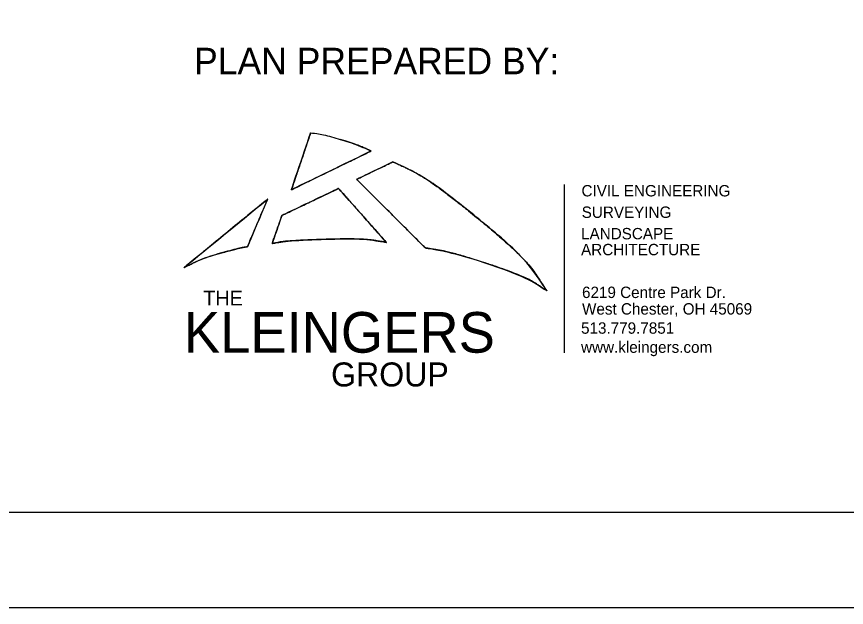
# Model space of a CAD drawing. Extents: x 44.2 to 78.2, y 4.5 to 26.5.
# Drawn here: x 46.547 to 50.92, y 4.501 to 7.613 of the extents above; entities that cross this region are included whole.
import ezdxf

# ---------------------------------------------------------------- set-up
doc = ezdxf.new("R2010")
doc.units = 0
for name, color, linetype in [('SH_Border', 7, 'Continuous'), ('SH_Cut_Line', 7, 'Continuous'), ('SH_Text', 7, 'Continuous')]:
    doc.layers.add(name, color=color, linetype=linetype)

msp = doc.modelspace()

# ---------------------------------------------------------------- linework, layer by layer
at = {"layer": 'SH_Border'}
msp.add_lwpolyline([(45.7359, 26.0014), (77.7359, 26.0014), (77.7359, 5.0014), (45.7359, 5.0014)], close=True, dxfattribs=at)
at = {"layer": 'SH_Cut_Line'}
msp.add_lwpolyline([(44.2359, 4.5014), (78.2359, 4.5014), (78.2359, 26.5014), (44.2359, 26.5014)], close=True, dxfattribs=at)
at = {"layer": 'SH_Text'}
msp.add_lwpolyline([(49.4332, 6.7295), (49.4332, 5.8423)], dxfattribs=at)
for points, degree in [([(48.0961, 7.0007), (48.0961, 7.0007), (47.9952, 6.7014), (47.9952, 6.7014)], 2), ([(48.4147, 6.905), (48.4147, 6.905), (48.3457, 6.9381), (48.2523, 6.9661), (48.159, 6.9941), (48.0961, 7.0007), (48.0961, 7.0007), (48.0961, 7.0007), (47.9952, 6.7014), (47.9952, 6.7014), (47.9952, 6.7014), (48.4147, 6.905), (48.4147, 6.905)], 3), ([(48.4147, 6.905), (48.4147, 6.905), (48.3457, 6.9381), (48.2523, 6.9661)], 2), ([(47.9952, 6.7014), (47.9952, 6.7014), (48.4147, 6.905), (48.4147, 6.905)], 2), ([(48.339, 6.7559), (48.339, 6.7559), (48.5295, 6.848), (48.5295, 6.848)], 2), ([(49.0087, 6.3182), (48.8407, 6.3724), (48.7005, 6.395), (48.7005, 6.395), (48.7005, 6.395), (48.339, 6.7559), (48.339, 6.7559), (48.339, 6.7559), (48.5295, 6.848), (48.5295, 6.848), (48.5295, 6.848), (48.7102, 6.7656), (48.9282, 6.5904), (49.2152, 6.3598), (49.3405, 6.1696), (49.3405, 6.1696), (49.3405, 6.1696), (49.2186, 6.2503), (49.0087, 6.3182)], 3), ([(48.5295, 6.848), (48.5295, 6.848), (48.7102, 6.7656), (48.9282, 6.5904)], 2), ([(48.7005, 6.395), (48.7005, 6.395), (48.339, 6.7559), (48.339, 6.7559)], 2), ([(48.2431, 6.7081), (48.2431, 6.7081), (48.495, 6.4242), (48.495, 6.4242), (48.495, 6.4242), (48.3623, 6.446), (48.1785, 6.4403), (47.9751, 6.4339), (47.8931, 6.4176), (47.8931, 6.4176), (47.8931, 6.4176), (47.945, 6.566), (47.945, 6.566), (47.945, 6.566), (48.2431, 6.7081), (48.2431, 6.7081)], 3), ([(47.945, 6.566), (47.945, 6.566), (48.2431, 6.7081), (48.2431, 6.7081)], 2), ([(48.2431, 6.7081), (48.2431, 6.7081), (48.495, 6.4242), (48.495, 6.4242)], 2), ([(47.8695, 6.6517), (47.8695, 6.6517), (47.428, 6.2904), (47.428, 6.2904)], 2), ([(47.8695, 6.6517), (47.8695, 6.6517), (47.428, 6.2904), (47.428, 6.2904), (47.428, 6.2904), (47.5272, 6.3411), (47.6346, 6.3706), (47.7313, 6.3972), (47.7632, 6.4008), (47.7632, 6.4008), (47.7632, 6.4008), (47.8695, 6.6517), (47.8695, 6.6517)], 3), ([(47.7632, 6.4008), (47.7632, 6.4008), (47.8695, 6.6517), (47.8695, 6.6517)], 2), ([(47.8931, 6.4176), (47.8931, 6.4176), (47.945, 6.566), (47.945, 6.566)], 2), ([(48.9282, 6.5904), (49.2152, 6.3598), (49.3405, 6.1696), (49.3405, 6.1696)], 2), ([(48.1785, 6.4403), (47.9751, 6.4339), (47.8931, 6.4176), (47.8931, 6.4176)], 2), ([(48.495, 6.4242), (48.495, 6.4242), (48.3623, 6.446), (48.1785, 6.4403)], 2), ([(47.6346, 6.3706), (47.7313, 6.3972), (47.7632, 6.4008), (47.7632, 6.4008)], 2), ([(49.0087, 6.3182), (48.8407, 6.3724), (48.7005, 6.395), (48.7005, 6.395)], 2), ([(47.428, 6.2904), (47.428, 6.2904), (47.5272, 6.3411), (47.6346, 6.3706)], 2), ([(49.3405, 6.1696), (49.3405, 6.1696), (49.2186, 6.2503), (49.0087, 6.3182)], 2)]:
    msp.add_open_spline(points, degree=degree, dxfattribs=at)

# ---------------------------------------------------------------- texts
for s, height, p in [('PLAN PREPARED BY:', 0.14, (47.4818, 7.3091)), ('CIVIL ENGINEERING', 0.06, (49.5238, 6.6661)), ('SURVEYING', 0.06, (49.5249, 6.5529)), ('LANDSCAPE', 0.06, (49.5215, 6.44)), ('ARCHITECTURE', 0.06, (49.5215, 6.3562)), ('THE', 0.07787, (47.5305, 6.0917)), ('6219 Centre Park Dr.', 0.06, (49.5266, 6.1309)), ('West Chester, OH 45069', 0.06, (49.5266, 6.0438)), ('KLEINGERS', 0.21415, (47.428, 5.843)), ('513.779.7851', 0.06, (49.5215, 5.9429)), ('www.kleingers.com', 0.06, (49.5215, 5.8423)), ('GROUP', 0.12654, (48.2039, 5.6651))]:
    msp.add_text(s, height=height, dxfattribs=at).set_placement(p)

doc.saveas('drawing.dxf')
